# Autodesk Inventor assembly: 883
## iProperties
Author: Vincent Molino
Shininess: 64.0
Angle Display Precision: 2
Document Length Units: 11272
Document Angle Units: 11286
Document Time Units: 11279
Document Mass Units: 11290
Document Length Units Precision: 3
Document Angle Units Precision: 2
Compacted: True
PropertySet Name: _Private Model Information
Created: 2002-05
Part Number: 883
Document SubType Name: Assembly
Designer: Vincent Molino
Control State: 0
Master: False
Checked Out: False
PropertySet Name: Design Tracking Control
Density: 0.0
Volumn: 0.0
Area: 0.0
PropertySet Name: Model Information
